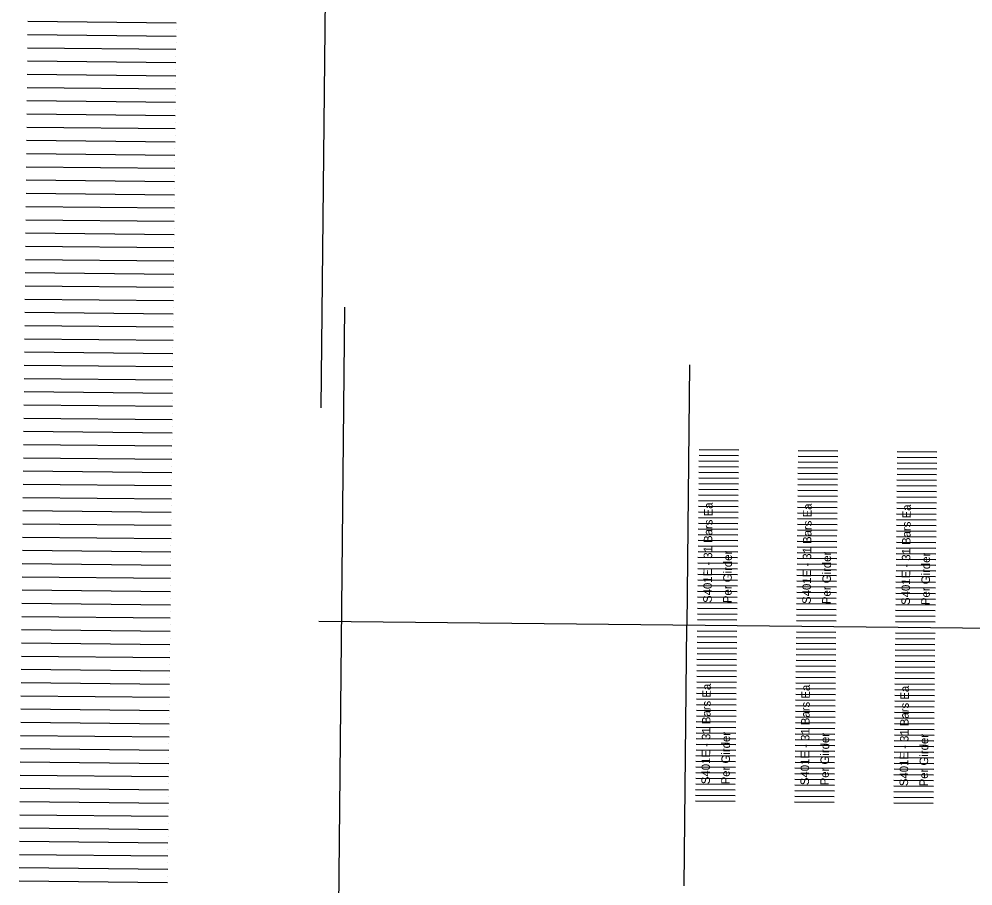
# Model space of a CAD drawing. Extents: x 632547 to 633311, y 380830 to 386139.
# Drawn here: x 633072.9 to 633157.1, y 381267.2 to 381343.8 of the extents above; entities that cross this region are included whole.
import ezdxf

# ---------------------------------------------------------------- set-up
doc = ezdxf.new("R2010")
doc.units = 0
for name, color, linetype in [('B_Border', 7, 'Continuous'), ('R_Border_Scale', 7, 'Continuous'), ('R_Wall', 7, 'Continuous')]:
    doc.layers.add(name, color=color, linetype=linetype)

msp = doc.modelspace()

# ---------------------------------------------------------------- linework, layer by layer
at = {"layer": 'B_Border'}
msp.add_line((633216.37, 381289.395), (633099.316, 381290.579), dxfattribs=at)
at = {"layer": 'R_Border_Scale'}
for p, q in [((633100.114, 381369.463), (633099.507, 381309.466)), ((633086.738, 381343.41), (633073.627, 381343.543)), ((633086.738, 381343.41), (633086.738, 381343.41)), ((633086.726, 381342.243), (633073.615, 381342.375)), ((633086.726, 381342.243), (633086.726, 381342.243)), ((633086.732, 381342.826), (633086.732, 381342.826)), ((633086.715, 381341.075), (633073.603, 381341.208)), ((633086.72, 381341.659), (633086.72, 381341.659)), ((633086.709, 381340.492), (633086.709, 381340.492)), ((633086.715, 381341.075), (633086.715, 381341.075)), ((633086.703, 381339.908), (633073.592, 381340.041)), ((633086.703, 381339.908), (633086.703, 381339.908)), ((633086.691, 381338.741), (633073.58, 381338.873)), ((633086.691, 381338.741), (633086.691, 381338.741)), ((633086.697, 381339.324), (633086.697, 381339.324)), ((633086.685, 381338.157), (633086.685, 381338.157)), ((633086.679, 381337.573), (633073.568, 381337.706)), ((633086.673, 381336.989), (633086.673, 381336.989)), ((633086.679, 381337.573), (633086.679, 381337.573)), ((633086.667, 381336.406), (633073.556, 381336.538)), ((633086.667, 381336.406), (633086.667, 381336.406)), ((633086.655, 381335.238), (633073.544, 381335.371)), ((633086.661, 381335.822), (633086.661, 381335.822)), ((633086.65, 381334.655), (633086.65, 381334.655)), ((633086.655, 381335.238), (633086.655, 381335.238)), ((633086.644, 381334.071), (633073.533, 381334.204)), ((633086.644, 381334.071), (633086.644, 381334.071)), ((633086.632, 381332.904), (633073.521, 381333.036)), ((633086.632, 381332.904), (633086.632, 381332.904)), ((633086.638, 381333.487), (633086.638, 381333.487)), ((633086.626, 381332.32), (633086.626, 381332.32)), ((633086.62, 381331.736), (633073.509, 381331.869)), ((633086.614, 381331.153), (633086.614, 381331.153)), ((633086.62, 381331.736), (633086.62, 381331.736)), ((633086.608, 381330.569), (633073.497, 381330.702)), ((633086.608, 381330.569), (633086.608, 381330.569)), ((633086.596, 381329.402), (633073.485, 381329.534)), ((633086.596, 381329.402), (633086.596, 381329.402)), ((633086.602, 381329.985), (633086.602, 381329.985)), ((633086.591, 381328.818), (633086.591, 381328.818)), ((633086.585, 381328.234), (633073.473, 381328.367)), ((633086.585, 381328.234), (633086.585, 381328.234)), ((633086.573, 381327.067), (633073.462, 381327.2)), ((633086.573, 381327.067), (633086.573, 381327.067)), ((633086.579, 381327.651), (633086.579, 381327.651)), ((633086.561, 381325.9), (633073.45, 381326.032)), ((633086.567, 381326.483), (633086.567, 381326.483)), ((633086.555, 381325.316), (633086.555, 381325.316)), ((633086.561, 381325.9), (633086.561, 381325.9)), ((633086.549, 381324.732), (633073.438, 381324.865)), ((633086.549, 381324.732), (633086.549, 381324.732)), ((633086.537, 381323.565), (633073.426, 381323.698)), ((633086.537, 381323.565), (633086.537, 381323.565)), ((633086.543, 381324.149), (633086.543, 381324.149)), ((633086.531, 381322.981), (633086.531, 381322.981)), ((633086.526, 381322.398), (633073.414, 381322.53)), ((633086.52, 381321.814), (633086.52, 381321.814)), ((633086.526, 381322.398), (633086.526, 381322.398)), ((633086.514, 381321.23), (633073.403, 381321.363)), ((633086.514, 381321.23), (633086.514, 381321.23)), ((633086.502, 381320.063), (633073.391, 381320.195)), ((633086.508, 381320.646), (633086.508, 381320.646)), ((633086.496, 381319.479), (633086.496, 381319.479)), ((633086.502, 381320.063), (633086.502, 381320.063)), ((633086.49, 381318.895), (633073.379, 381319.028)), ((633086.49, 381318.895), (633086.49, 381318.895)), ((633086.478, 381317.728), (633073.367, 381317.861)), ((633086.478, 381317.728), (633086.478, 381317.728)), ((633086.484, 381318.312), (633086.484, 381318.312)), ((633101.597, 381318.335), (633100.99, 381258.338)), ((633086.472, 381317.144), (633086.472, 381317.144)), ((633086.467, 381316.561), (633073.355, 381316.693)), ((633086.461, 381315.977), (633086.461, 381315.977)), ((633086.467, 381316.561), (633086.467, 381316.561)), ((633086.455, 381315.393), (633073.344, 381315.526)), ((633086.455, 381315.393), (633086.455, 381315.393)), ((633086.443, 381314.226), (633073.332, 381314.359)), ((633086.449, 381314.81), (633086.449, 381314.81)), ((633086.437, 381313.642), (633086.437, 381313.642)), ((633086.443, 381314.226), (633086.443, 381314.226)), ((633086.431, 381313.059), (633073.32, 381313.191)), ((633086.431, 381313.059), (633086.431, 381313.059)), ((633132.051, 381313.249), (633131.819, 381290.251)), ((633086.419, 381311.891), (633073.308, 381312.024)), ((633086.419, 381311.891), (633086.419, 381311.891)), ((633086.425, 381312.475), (633086.425, 381312.475)), ((633086.413, 381311.308), (633086.413, 381311.308)), ((633086.407, 381310.724), (633073.296, 381310.857)), ((633086.402, 381310.14), (633086.402, 381310.14)), ((633086.407, 381310.724), (633086.407, 381310.724)), ((633086.396, 381309.557), (633073.285, 381309.689)), ((633086.396, 381309.557), (633086.396, 381309.557)), ((633086.384, 381308.389), (633073.273, 381308.522)), ((633086.384, 381308.389), (633086.384, 381308.389)), ((633086.39, 381308.973), (633086.39, 381308.973)), ((633086.378, 381307.806), (633086.378, 381307.806)), ((633086.372, 381307.222), (633073.261, 381307.355)), ((633086.372, 381307.222), (633086.372, 381307.222)), ((633086.36, 381306.055), (633073.249, 381306.187)), ((633086.36, 381306.055), (633086.36, 381306.055)), ((633086.366, 381306.638), (633086.366, 381306.638)), ((633086.348, 381304.887), (633073.237, 381305.02)), ((633086.354, 381305.471), (633086.354, 381305.471)), ((633136.401, 381305.205), (633132.901, 381305.24)), ((633136.406, 381305.705), (633132.906, 381305.74)), ((633145.15, 381305.116), (633141.651, 381305.152)), ((633145.155, 381305.616), (633141.656, 381305.652)), ((633153.9, 381305.028), (633150.4, 381305.063)), ((633153.905, 381305.528), (633150.405, 381305.563)), ((633086.343, 381304.304), (633086.343, 381304.304)), ((633086.348, 381304.887), (633086.348, 381304.887)), ((633136.391, 381304.205), (633132.891, 381304.24)), ((633136.396, 381304.705), (633132.896, 381304.74)), ((633145.14, 381304.117), (633141.64, 381304.152)), ((633145.145, 381304.617), (633141.646, 381304.652)), ((633153.895, 381304.528), (633150.395, 381304.563)), ((633086.337, 381303.72), (633073.225, 381303.852)), ((633086.337, 381303.72), (633086.337, 381303.72)), ((633136.386, 381303.705), (633132.886, 381303.74)), ((633145.135, 381303.617), (633141.635, 381303.652)), ((633153.885, 381303.528), (633150.385, 381303.563)), ((633153.89, 381304.028), (633150.39, 381304.063)), ((633086.325, 381302.552), (633073.214, 381302.685)), ((633086.325, 381302.552), (633086.325, 381302.552)), ((633086.331, 381303.136), (633086.331, 381303.136)), ((633136.376, 381302.705), (633132.876, 381302.741)), ((633136.381, 381303.205), (633132.881, 381303.241)), ((633145.125, 381302.617), (633141.625, 381302.652)), ((633145.13, 381303.117), (633141.63, 381303.152)), ((633153.875, 381302.528), (633150.375, 381302.564)), ((633153.88, 381303.028), (633150.38, 381303.063)), ((633086.319, 381301.969), (633086.319, 381301.969)), ((633136.365, 381301.705), (633132.866, 381301.741)), ((633136.371, 381302.205), (633132.871, 381302.241)), ((633145.115, 381301.617), (633141.615, 381301.652)), ((633145.12, 381302.117), (633141.62, 381302.152)), ((633153.87, 381302.028), (633150.37, 381302.064)), ((633086.313, 381301.385), (633073.202, 381301.518)), ((633086.307, 381300.801), (633086.307, 381300.801)), ((633086.313, 381301.385), (633086.313, 381301.385)), ((633136.36, 381301.205), (633132.861, 381301.241)), ((633145.11, 381301.117), (633141.61, 381301.152)), ((633153.86, 381301.028), (633150.36, 381301.064)), ((633153.865, 381301.528), (633150.365, 381301.564)), ((633086.301, 381300.218), (633073.19, 381300.35)), ((633086.301, 381300.218), (633086.301, 381300.218)), ((633136.35, 381300.205), (633132.85, 381300.241)), ((633136.355, 381300.705), (633132.856, 381300.741)), ((633145.1, 381300.117), (633141.6, 381300.152)), ((633145.105, 381300.617), (633141.605, 381300.652)), ((633153.849, 381300.028), (633150.35, 381300.064)), ((633153.854, 381300.528), (633150.355, 381300.564)), ((633086.289, 381299.05), (633073.178, 381299.183)), ((633086.295, 381299.634), (633086.295, 381299.634)), ((633136.34, 381299.205), (633132.84, 381299.241)), ((633136.345, 381299.705), (633132.845, 381299.741)), ((633145.09, 381299.117), (633141.59, 381299.152)), ((633145.095, 381299.617), (633141.595, 381299.652)), ((633153.844, 381299.528), (633150.345, 381299.564)), ((633086.283, 381298.467), (633086.283, 381298.467)), ((633086.289, 381299.05), (633086.289, 381299.05)), ((633136.33, 381298.205), (633132.83, 381298.241)), ((633136.335, 381298.705), (633132.835, 381298.741)), ((633145.085, 381298.617), (633141.585, 381298.652)), ((633153.834, 381298.528), (633150.334, 381298.564)), ((633153.839, 381299.028), (633150.339, 381299.064)), ((633086.278, 381297.883), (633073.166, 381298.016)), ((633086.278, 381297.883), (633086.278, 381297.883)), ((633136.325, 381297.705), (633132.825, 381297.741)), ((633145.075, 381297.617), (633141.575, 381297.652)), ((633145.08, 381298.117), (633141.58, 381298.152)), ((633153.824, 381297.528), (633150.324, 381297.564)), ((633153.829, 381298.028), (633150.329, 381298.064)), ((633086.266, 381296.716), (633073.155, 381296.848)), ((633086.266, 381296.716), (633086.266, 381296.716)), ((633086.272, 381297.299), (633086.272, 381297.299)), ((633136.315, 381296.705), (633132.815, 381296.741)), ((633136.32, 381297.205), (633132.82, 381297.241)), ((633145.064, 381296.617), (633141.565, 381296.652)), ((633145.069, 381297.117), (633141.57, 381297.152)), ((633153.814, 381296.528), (633150.314, 381296.564)), ((633153.819, 381297.028), (633150.319, 381297.064)), ((633086.26, 381296.132), (633086.26, 381296.132)), ((633136.305, 381295.705), (633132.805, 381295.741)), ((633136.31, 381296.205), (633132.81, 381296.241)), ((633145.059, 381296.117), (633141.56, 381296.152)), ((633153.809, 381296.028), (633150.309, 381296.064)), ((633086.254, 381295.548), (633073.143, 381295.681)), ((633086.248, 381294.965), (633086.248, 381294.965)), ((633086.254, 381295.548), (633086.254, 381295.548)), ((633136.3, 381295.206), (633132.8, 381295.241)), ((633145.049, 381295.117), (633141.549, 381295.152)), ((633145.054, 381295.617), (633141.554, 381295.652)), ((633153.799, 381295.028), (633150.299, 381295.064)), ((633153.804, 381295.528), (633150.304, 381295.564)), ((633086.242, 381294.381), (633073.131, 381294.514)), ((633086.242, 381294.381), (633086.242, 381294.381)), ((633136.29, 381294.206), (633132.79, 381294.241)), ((633136.295, 381294.706), (633132.795, 381294.741)), ((633145.039, 381294.117), (633141.539, 381294.152)), ((633145.044, 381294.617), (633141.544, 381294.652)), ((633153.789, 381294.029), (633150.289, 381294.064)), ((633153.794, 381294.529), (633150.294, 381294.564)), ((633086.23, 381293.214), (633073.119, 381293.346)), ((633086.23, 381293.214), (633086.23, 381293.214)), ((633086.236, 381293.797), (633086.236, 381293.797)), ((633136.279, 381293.206), (633132.78, 381293.241)), ((633136.285, 381293.706), (633132.785, 381293.741)), ((633145.034, 381293.617), (633141.534, 381293.652)), ((633153.784, 381293.529), (633150.284, 381293.564)), ((633086.224, 381292.63), (633086.224, 381292.63)), ((633136.274, 381292.706), (633132.775, 381292.741)), ((633145.024, 381292.617), (633141.524, 381292.653)), ((633145.029, 381293.117), (633141.529, 381293.153)), ((633153.774, 381292.529), (633150.274, 381292.564)), ((633153.779, 381293.029), (633150.279, 381293.064)), ((633086.219, 381292.046), (633073.107, 381292.179)), ((633086.219, 381292.046), (633086.219, 381292.046)), ((633136.264, 381291.706), (633132.764, 381291.741)), ((633136.269, 381292.206), (633132.77, 381292.241)), ((633145.014, 381291.617), (633141.514, 381291.653)), ((633145.019, 381292.117), (633141.519, 381292.153)), ((633153.763, 381291.529), (633150.264, 381291.564)), ((633153.768, 381292.029), (633150.269, 381292.064)), ((633086.207, 381290.879), (633073.096, 381291.012)), ((633086.207, 381290.879), (633086.207, 381290.879)), ((633086.213, 381291.463), (633086.213, 381291.463)), ((633136.254, 381290.706), (633132.754, 381290.741)), ((633136.259, 381291.206), (633132.759, 381291.241)), ((633145.004, 381290.617), (633141.504, 381290.653)), ((633145.009, 381291.117), (633141.509, 381291.153)), ((633153.758, 381291.029), (633150.259, 381291.064)), ((633086.195, 381289.712), (633073.084, 381289.844)), ((633086.201, 381290.295), (633086.201, 381290.295)), ((633131.586, 381267.252), (633131.819, 381290.251)), ((633153.753, 381290.529), (633150.253, 381290.564)), ((633086.189, 381289.128), (633086.189, 381289.128)), ((633086.195, 381289.712), (633086.195, 381289.712)), ((633136.239, 381289.206), (633132.739, 381289.241)), ((633136.244, 381289.706), (633132.744, 381289.741)), ((633144.989, 381289.117), (633141.489, 381289.153)), ((633144.994, 381289.617), (633141.494, 381289.653)), ((633153.738, 381289.029), (633150.238, 381289.064)), ((633153.743, 381289.529), (633150.243, 381289.564)), ((633086.183, 381288.544), (633073.072, 381288.677)), ((633086.183, 381288.544), (633086.183, 381288.544)), ((633136.229, 381288.206), (633132.729, 381288.241)), ((633136.234, 381288.706), (633132.734, 381288.741)), ((633144.978, 381288.117), (633141.479, 381288.153)), ((633144.984, 381288.617), (633141.484, 381288.653)), ((633153.733, 381288.529), (633150.233, 381288.564)), ((633086.171, 381287.377), (633073.06, 381287.51)), ((633086.171, 381287.377), (633086.171, 381287.377)), ((633086.177, 381287.961), (633086.177, 381287.961)), ((633136.224, 381287.706), (633132.724, 381287.741)), ((633144.973, 381287.617), (633141.474, 381287.653)), ((633153.723, 381287.529), (633150.223, 381287.564)), ((633153.728, 381288.029), (633150.228, 381288.064)), ((633086.165, 381286.793), (633086.165, 381286.793)), ((633136.214, 381286.706), (633132.714, 381286.741)), ((633136.219, 381287.206), (633132.719, 381287.241)), ((633144.963, 381286.617), (633141.463, 381286.653)), ((633144.968, 381287.117), (633141.469, 381287.153)), ((633153.713, 381286.529), (633150.213, 381286.564)), ((633153.718, 381287.029), (633150.218, 381287.064)), ((633086.159, 381286.209), (633073.048, 381286.342)), ((633086.154, 381285.626), (633086.154, 381285.626)), ((633086.159, 381286.209), (633086.159, 381286.209)), ((633136.204, 381285.706), (633132.704, 381285.741)), ((633136.209, 381286.206), (633132.709, 381286.241)), ((633144.953, 381285.617), (633141.453, 381285.653)), ((633144.958, 381286.117), (633141.458, 381286.153)), ((633153.708, 381286.029), (633150.208, 381286.064)), ((633086.148, 381285.042), (633073.037, 381285.175)), ((633086.148, 381285.042), (633086.148, 381285.042)), ((633136.199, 381285.206), (633132.699, 381285.241)), ((633144.948, 381285.118), (633141.448, 381285.153)), ((633153.698, 381285.029), (633150.198, 381285.064)), ((633153.703, 381285.529), (633150.203, 381285.564)), ((633086.136, 381283.875), (633073.025, 381284.007)), ((633086.142, 381284.458), (633086.142, 381284.458)), ((633136.188, 381284.206), (633132.689, 381284.241)), ((633136.193, 381284.706), (633132.694, 381284.741)), ((633144.938, 381284.118), (633141.438, 381284.153)), ((633144.943, 381284.618), (633141.443, 381284.653)), ((633153.688, 381284.029), (633150.188, 381284.064)), ((633153.693, 381284.529), (633150.193, 381284.564)), ((633086.13, 381283.291), (633086.13, 381283.291)), ((633086.136, 381283.875), (633086.136, 381283.875)), ((633136.178, 381283.206), (633132.678, 381283.242)), ((633136.183, 381283.706), (633132.684, 381283.742)), ((633144.928, 381283.118), (633141.428, 381283.153)), ((633144.933, 381283.618), (633141.433, 381283.653)), ((633153.682, 381283.529), (633150.183, 381283.564)), ((633086.124, 381282.707), (633073.013, 381282.84)), ((633086.124, 381282.707), (633086.124, 381282.707)), ((633136.168, 381282.206), (633132.668, 381282.242)), ((633136.173, 381282.706), (633132.673, 381282.742)), ((633144.923, 381282.618), (633141.423, 381282.653)), ((633153.672, 381282.529), (633150.173, 381282.565)), ((633153.677, 381283.029), (633150.178, 381283.064)), ((633086.112, 381281.54), (633073.001, 381281.673)), ((633086.112, 381281.54), (633086.112, 381281.54)), ((633086.118, 381282.124), (633086.118, 381282.124)), ((633136.163, 381281.706), (633132.663, 381281.742)), ((633144.913, 381281.618), (633141.413, 381281.653)), ((633144.918, 381282.118), (633141.418, 381282.153)), ((633153.662, 381281.529), (633150.162, 381281.565)), ((633153.667, 381282.029), (633150.167, 381282.065)), ((633086.106, 381280.956), (633086.106, 381280.956)), ((633136.153, 381280.706), (633132.653, 381280.742)), ((633136.158, 381281.206), (633132.658, 381281.242)), ((633144.903, 381280.618), (633141.403, 381280.653)), ((633144.908, 381281.118), (633141.408, 381281.153)), ((633153.652, 381280.529), (633150.152, 381280.565)), ((633153.657, 381281.029), (633150.157, 381281.065)), ((633086.1, 381280.373), (633072.989, 381280.505)), ((633086.095, 381279.789), (633086.095, 381279.789)), ((633086.1, 381280.373), (633086.1, 381280.373)), ((633136.143, 381279.706), (633132.643, 381279.742)), ((633136.148, 381280.206), (633132.648, 381280.242)), ((633144.898, 381280.118), (633141.398, 381280.153)), ((633153.647, 381280.029), (633150.147, 381280.065)), ((633086.089, 381279.205), (633072.977, 381279.338)), ((633086.089, 381279.205), (633086.089, 381279.205)), ((633136.138, 381279.206), (633132.638, 381279.242)), ((633144.887, 381279.118), (633141.388, 381279.153)), ((633144.892, 381279.618), (633141.393, 381279.653)), ((633153.637, 381279.029), (633150.137, 381279.065)), ((633153.642, 381279.529), (633150.142, 381279.565)), ((633086.077, 381278.038), (633072.966, 381278.171)), ((633086.077, 381278.038), (633086.077, 381278.038)), ((633086.083, 381278.622), (633086.083, 381278.622)), ((633136.128, 381278.206), (633132.628, 381278.242)), ((633136.133, 381278.706), (633132.633, 381278.742)), ((633144.877, 381278.118), (633141.377, 381278.153)), ((633144.882, 381278.618), (633141.383, 381278.653)), ((633153.627, 381278.029), (633150.127, 381278.065)), ((633153.632, 381278.529), (633150.132, 381278.565)), ((633086.071, 381277.454), (633086.071, 381277.454)), ((633136.118, 381277.206), (633132.618, 381277.242)), ((633136.123, 381277.706), (633132.623, 381277.742)), ((633144.872, 381277.618), (633141.372, 381277.653)), ((633153.622, 381277.529), (633150.122, 381277.565)), ((633086.065, 381276.871), (633072.954, 381277.003)), ((633086.065, 381276.871), (633086.065, 381276.871)), ((633136.113, 381276.706), (633132.613, 381276.742)), ((633144.862, 381276.618), (633141.362, 381276.653)), ((633144.867, 381277.118), (633141.367, 381277.153)), ((633153.612, 381276.529), (633150.112, 381276.565)), ((633153.617, 381277.029), (633150.117, 381277.065)), ((633086.053, 381275.703), (633072.942, 381275.836)), ((633086.053, 381275.703), (633086.053, 381275.703)), ((633086.059, 381276.287), (633086.059, 381276.287)), ((633136.102, 381275.707), (633132.603, 381275.742)), ((633136.107, 381276.206), (633132.608, 381276.242)), ((633144.852, 381275.618), (633141.352, 381275.653)), ((633144.857, 381276.118), (633141.357, 381276.153)), ((633153.602, 381275.529), (633150.102, 381275.565)), ((633153.607, 381276.029), (633150.107, 381276.065)), ((633086.041, 381274.536), (633072.93, 381274.669)), ((633086.047, 381275.12), (633086.047, 381275.12)), ((633136.092, 381274.707), (633132.592, 381274.742)), ((633136.097, 381275.207), (633132.598, 381275.242)), ((633144.842, 381274.618), (633141.342, 381274.653)), ((633144.847, 381275.118), (633141.347, 381275.153)), ((633153.596, 381275.03), (633150.097, 381275.065)), ((633086.035, 381273.952), (633086.035, 381273.952)), ((633086.041, 381274.536), (633086.041, 381274.536)), ((633153.591, 381274.53), (633150.092, 381274.565)), ((633086.03, 381273.369), (633072.918, 381273.501)), ((633086.03, 381273.369), (633086.03, 381273.369)), ((633086.018, 381272.201), (633072.907, 381272.334)), ((633086.018, 381272.201), (633086.018, 381272.201)), ((633086.024, 381272.785), (633086.024, 381272.785)), ((633086.012, 381271.618), (633086.012, 381271.618)), ((633086.006, 381271.034), (633072.895, 381271.167)), ((633086, 381270.45), (633086, 381270.45)), ((633086.006, 381271.034), (633086.006, 381271.034)), ((633085.994, 381269.867), (633072.883, 381269.999)), ((633085.994, 381269.867), (633085.994, 381269.867)), ((633085.982, 381268.699), (633072.871, 381268.832)), ((633085.988, 381269.283), (633085.988, 381269.283)), ((633085.976, 381268.115), (633085.976, 381268.115)), ((633085.982, 381268.699), (633085.982, 381268.699)), ((633085.971, 381267.532), (633072.859, 381267.664)), ((633085.971, 381267.532), (633085.971, 381267.532))]:
    msp.add_line(p, q, dxfattribs=at)

# ---------------------------------------------------------------- texts
at = {"layer": 'R_Wall'}
for s, p in [('S401E - 31 Bars Ea,', (633134.019, 381292.228)), ('S401E - 31 Bars Ea,', (633142.769, 381292.14)), ('S401E - 31 Bars Ea,', (633151.519, 381292.051)), ('Per Girder', (633135.769, 381292.211)), ('Per Girder', (633144.519, 381292.122)), ('Per Girder', (633153.268, 381292.034)), ('S401E - 31 Bars Ea,', (633133.858, 381276.229)), ('S401E - 31 Bars Ea,', (633142.607, 381276.141)), ('S401E - 31 Bars Ea,', (633151.357, 381276.052)), ('Per Girder', (633135.608, 381276.212)), ('Per Girder', (633144.357, 381276.123)), ('Per Girder', (633153.107, 381276.035))]:
    msp.add_text(s, height=0.75, rotation=89.43036, dxfattribs=at).set_placement(p)

doc.saveas('drawing.dxf')
